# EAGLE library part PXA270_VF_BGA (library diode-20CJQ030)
Intel® PXA270 Processor PXA270 with VF-BGA package 13x13 Features: High-performance processor: -Intel XScale® microarchitecture with Intel® Wireless MMX? Technology -7 Stage pipeline -32 KB instruction cache -32 KB data cache -2 KB "mini" data cache -Extensive data buffering 256 Kbytes of internal SRAM for high speed code or data storage preserved during low-power states High-speed baseband processor interface (Mobile Scalable Link) Rich serial peripheral set: -AC?97 audio port -I2S audio port -USB Client controller -USB Host controller -USB On-The-Go controller -Three high-speed UARTs (two with hardware flow control) -FIR and SIR infrared communications port Hardware debug features ? IEEE JTAG interface with boundary scan Hardware performance-monitoring features with on-chip trace buffer Real-time clock Operating-system timers LCD Controller Universal Subscriber Identity Module interface Low power: -Wireless Intel Speedstep® Technology -Less than 500 mW typical internal dissipation -Supply voltage may be reduced to 0.85 V -Four low-power modes -Dynamic voltage and frequencymanagement High-performance memory controller: -Four banks of SDRAM: up to 104 MHz @ 2.5V, 3.0V, and 3.3V I/O interface -Six static chip selects -Support for PCMCIA and Compact Flash -Companion chip interface Flexible clocking: -CPU clock from 104 to 624 MHz -Flexible memory clock ratios -Frequency changes -Functional clock gating Additional peripherals for system connectivity: -SD Card / MMC Controller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
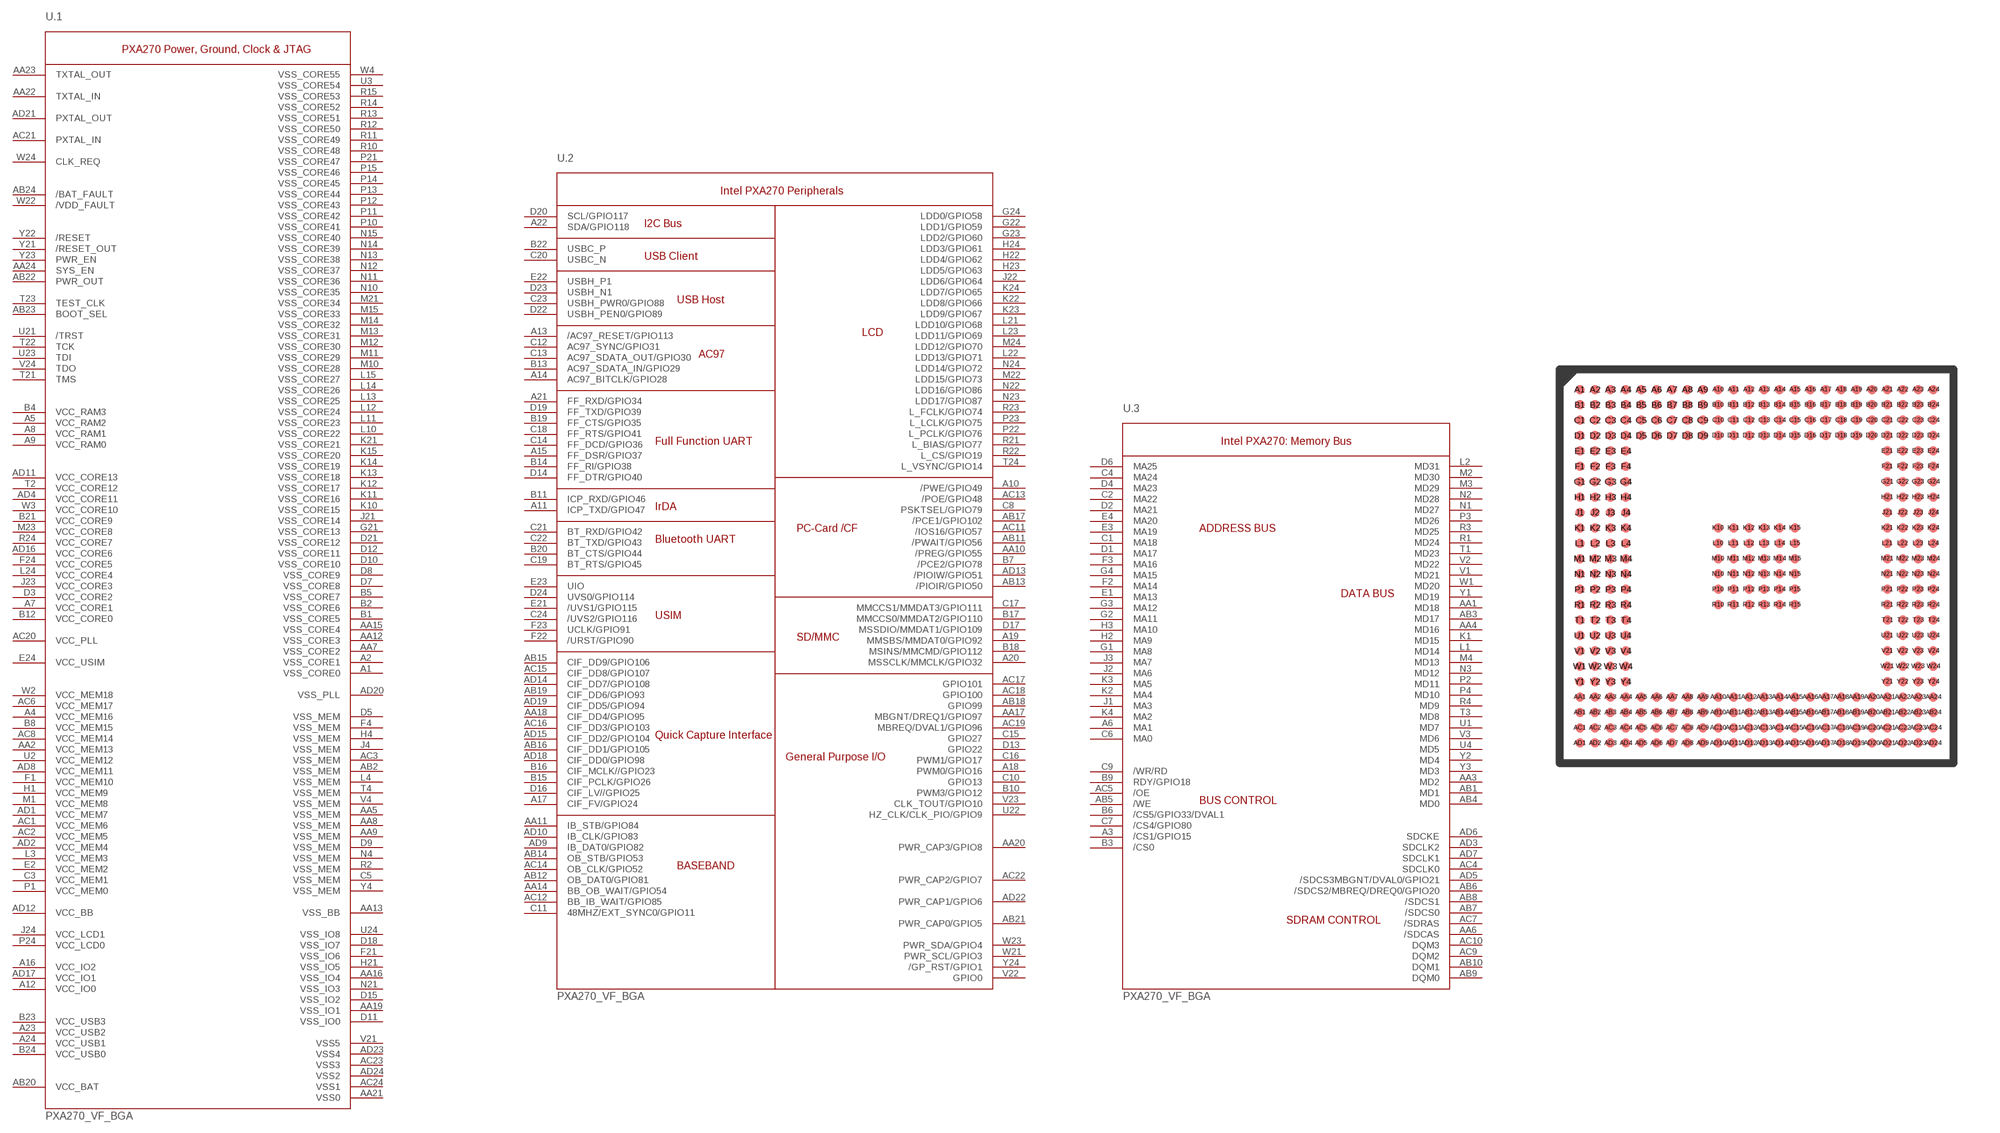
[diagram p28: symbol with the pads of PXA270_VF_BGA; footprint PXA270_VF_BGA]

Designator prefix U; gates .2=PXA270_PERIPHERALS .3=PXA_270_MEM_BUS .1=PXA270_PWR_CLK_13X13

## PXA270_VF_BGA  [PXA270_VF_BGA]
A1  .1:VSS_CORE0  pwr
A2  .1:VSS_CORE1  pwr
A3  .3:/CS1/GPIO15
A4  .1:VCC_MEM16  pwr
A5  .1:VCC_RAM2  pwr
A6  .3:MA1  out
A7  .1:VCC_CORE1  pwr
A8  .1:VCC_RAM1  pwr
A9  .1:VCC_RAM0  pwr
A10  .2:/PWE/GPIO49
A11  .2:ICP_TXD/GPIO47
A12  .1:VCC_IO0  pwr
A13  .2:/AC97_RESET/GPIO113
A14  .2:AC97_BITCLK/GPIO28
A15  .2:FF_DSR/GPIO37
A16  .1:VCC_IO2  pwr
A17  .2:CIF_FV/GPIO24
A18  .2:PWM0/GPIO16
A19  .2:MMSBS/MMDAT0/GPIO92
A20  .2:MSSCLK/MMCLK/GPIO32
A21  .2:FF_RXD/GPIO34
A22  .2:SDA/GPIO118
A23  .1:VCC_USB2  pwr
A24  .1:VCC_USB1  pwr
AA1  .3:MD18
AA2  .1:VCC_MEM13  pwr
AA3  .3:MD2
AA4  .3:MD16
AA5  .1:VSS_MEM  pwr
AA6  .3:/SDCAS  out
AA7  .1:VSS_CORE2  pwr
AA8  .1:VSS_MEM  pwr
AA9  .1:VSS_MEM  pwr
AA10  .2:/PREG/GPIO55
AA11  .2:IB_STB/GPIO84
AA12  .1:VSS_CORE3  pwr
AA13  .1:VSS_BB  pwr
AA14  .2:BB_OB_WAIT/GPIO54
AA15  .1:VSS_CORE4  pwr
AA16  .1:VSS_IO4  pwr
AA17  .2:MBGNT/DREQ1/GPIO97
AA18  .2:CIF_DD4/GPIO95
AA19  .1:VSS_IO1  pwr
AA20  .2:PWR_CAP3/GPIO8
AA21  .1:VSS0  pwr
AA22  .1:TXTAL_IN  in
AA23  .1:TXTAL_OUT  out
AA24  .1:SYS_EN
AB1  .3:MD1
AB2  .1:VSS_MEM  pwr
AB3  .3:MD17
AB4  .3:MD0
AB5  .3:/WE  out
AB6  .3:/SDCS2/MBREQ/DREQ0/GPIO20
AB7  .3:/SDCS0  out
AB8  .3:/SDCS1  out
AB9  .3:DQM0  out
AB10  .3:DQM1  out
AB11  .2:/PWAIT/GPIO56
AB12  .2:OB_DAT0/GPIO81
AB13  .2:/PIOIR/GPIO50
AB14  .2:OB_STB/GPIO53
AB15  .2:CIF_DD9/GPIO106
AB16  .2:CIF_DD1/GPIO105
AB17  .2:/PCE1/GPIO102
AB18  .2:GPIO99
AB19  .2:CIF_DD6/GPIO93
AB20  .1:VCC_BAT  pwr
AB21  .2:PWR_CAP0/GPIO5
AB22  .1:PWR_OUT  out
AB23  .1:BOOT_SEL  in
AB24  .1:/BAT_FAULT  in
AC1  .1:VCC_MEM6  pwr
AC2  .1:VCC_MEM5  pwr
AC3  .1:VSS_MEM  pwr
AC4  .3:SDCLK0  out
AC5  .3:/OE  out
AC6  .1:VCC_MEM17  pwr
AC7  .3:/SDRAS  out
AC8  .1:VCC_MEM14  pwr
AC9  .3:DQM2  out
AC10  .3:DQM3  out
AC11  .2:/IOS16/GPIO57
AC12  .2:BB_IB_WAIT/GPIO85
AC13  .2:/POE/GPIO48
AC14  .2:OB_CLK/GPIO52
AC15  .2:CIF_DD8/GPIO107
AC16  .2:CIF_DD3/GPIO103
AC17  .2:GPIO101
AC18  .2:GPIO100
AC19  .2:MBREQ/DVAL1/GPIO96
AC20  .1:VCC_PLL  pwr
AC21  .1:PXTAL_IN  in
AC22  .2:PWR_CAP2/GPIO7
AC23  .1:VSS3  pwr
AC24  .1:VSS1  pwr
AD1  .1:VCC_MEM7  pwr
AD2  .1:VCC_MEM4  pwr
AD3  .3:SDCLK2  out
AD4  .1:VCC_CORE11  pwr
AD5  .3:/SDCS3MBGNT/DVAL0/GPIO21
AD6  .3:SDCKE  out
AD7  .3:SDCLK1  out
AD8  .1:VCC_MEM11  pwr
AD9  .2:IB_DAT0/GPIO82
AD10  .2:IB_CLK/GPIO83
AD11  .1:VCC_CORE13  pwr
AD12  .1:VCC_BB  pwr
AD13  .2:/PIOIW/GPIO51
AD14  .2:CIF_DD7/GPIO108
AD15  .2:CIF_DD2/GPIO104
AD16  .1:VCC_CORE6  pwr
AD17  .1:VCC_IO1  pwr
AD18  .2:CIF_DD0/GPIO98
AD19  .2:CIF_DD5/GPIO94
AD20  .1:VSS_PLL  pwr
AD21  .1:PXTAL_OUT  out
AD22  .2:PWR_CAP1/GPIO6
AD23  .1:VSS4  pwr
AD24  .1:VSS2  pwr
B1  .1:VSS_CORE5  pwr
B2  .1:VSS_CORE6  pwr
B3  .3:/CS0  out
B4  .1:VCC_RAM3  pwr
B5  .1:VSS_CORE7  pwr
B6  .3:/CS5/GPIO33/DVAL1
B7  .2:/PCE2/GPIO78
B8  .1:VCC_MEM15  pwr
B9  .3:RDY/GPIO18
B10  .2:PWM3/GPIO12
B11  .2:ICP_RXD/GPIO46
B12  .1:VCC_CORE0  pwr
B13  .2:AC97_SDATA_IN/GPIO29
B14  .2:FF_RI/GPIO38
B15  .2:CIF_PCLK/GPIO26
B16  .2:CIF_MCLK//GPIO23
B17  .2:MMCCS0/MMDAT2/GPIO110
B18  .2:MSINS/MMCMD/GPIO112
B19  .2:FF_CTS/GPIO35
B20  .2:BT_CTS/GPIO44
B21  .1:VCC_CORE9  pwr
B22  .2:USBC_P
B23  .1:VCC_USB3  pwr
B24  .1:VCC_USB0  pwr
C1  .3:MA18  out
C2  .3:MA22  out
C3  .1:VCC_MEM1  pwr
C4  .3:MA24  out
C5  .1:VSS_MEM  pwr
C6  .3:MA0  out
C7  .3:/CS4/GPIO80
C8  .2:PSKTSEL/GPIO79
C9  .3:/WR/RD  out
C10  .2:GPIO13
C11  .2:48MHZ/EXT_SYNC0/GPIO11
C12  .2:AC97_SYNC/GPIO31
C13  .2:AC97_SDATA_OUT/GPIO30
C14  .2:FF_DCD/GPIO36
C15  .2:GPIO27
C16  .2:PWM1/GPIO17
C17  .2:MMCCS1/MMDAT3/GPIO111
C18  .2:FF_RTS/GPIO41
C19  .2:BT_RTS/GPIO45
C20  .2:USBC_N
C21  .2:BT_RXD/GPIO42
C22  .2:BT_TXD/GPIO43
C23  .2:USBH_PWR0/GPIO88
C24  .2:/UVS2/GPIO116
D1  .3:MA17  out
D2  .3:MA21  out
D3  .1:VCC_CORE2  pwr
D4  .3:MA23  out
D5  .1:VSS_MEM  pwr
D6  .3:MA25  out
D7  .1:VSS_CORE8  pwr
D8  .1:VSS_CORE9  pwr
D9  .1:VSS_MEM  pwr
D10  .1:VSS_CORE10  pwr
D11  .1:VSS_IO0  pwr
D12  .1:VSS_CORE11  pwr
D13  .2:GPIO22
D14  .2:FF_DTR/GPIO40
D15  .1:VSS_IO2  pwr
D16  .2:CIF_LV//GPIO25
D17  .2:MSSDIO/MMDAT1/GPIO109
D18  .1:VSS_IO7  pwr
D19  .2:FF_TXD/GPIO39
D20  .2:SCL/GPIO117
D21  .1:VSS_CORE12  pwr
D22  .2:USBH_PEN0/GPIO89
D23  .2:USBH_N1
D24  .2:UVS0/GPIO114
E1  .3:MA13  out
E2  .1:VCC_MEM2  pwr
E3  .3:MA19  out
E4  .3:MA20  out
E21  .2:/UVS1/GPIO115
E22  .2:USBH_P1
E23  .2:UIO
E24  .1:VCC_USIM  pwr
F1  .1:VCC_MEM10  pwr
F2  .3:MA14  out
F3  .3:MA16  out
F4  .1:VSS_MEM  pwr
F21  .1:VSS_IO6  pwr
F22  .2:/URST/GPIO90
F23  .2:UCLK/GPIO91
F24  .1:VCC_CORE5  pwr
G1  .3:MA8  out
G2  .3:MA11  out
G3  .3:MA12  out
G4  .3:MA15  out
G21  .1:VSS_CORE13  pwr
G22  .2:LDD1/GPIO59
G23  .2:LDD2/GPIO60
G24  .2:LDD0/GPIO58
H1  .1:VCC_MEM9  pwr
H2  .3:MA9  out
H3  .3:MA10  out
H4  .1:VSS_MEM  pwr
H21  .1:VSS_IO5  pwr
H22  .2:LDD4/GPIO62
H23  .2:LDD5/GPIO63
H24  .2:LDD3/GPIO61
J1  .3:MA3  out
J2  .3:MA6  out
J3  .3:MA7  out
J4  .1:VSS_MEM  pwr
J21  .1:VSS_CORE14  pwr
J22  .2:LDD6/GPIO64
J23  .1:VCC_CORE3  pwr
J24  .1:VCC_LCD1  pwr
K1  .3:MD15
K2  .3:MA4  out
K3  .3:MA5  out
K4  .3:MA2  out
K10  .1:VSS_CORE15  pwr
K11  .1:VSS_CORE16  pwr
K12  .1:VSS_CORE17  pwr
K13  .1:VSS_CORE18  pwr
K14  .1:VSS_CORE19  pwr
K15  .1:VSS_CORE20  pwr
K21  .1:VSS_CORE21  pwr
K22  .2:LDD8/GPIO66
K23  .2:LDD9/GPIO67
K24  .2:LDD7/GPIO65
L1  .3:MD14
L2  .3:MD31
L3  .1:VCC_MEM3  pwr
L4  .1:VSS_MEM  pwr
L10  .1:VSS_CORE22  pwr
L11  .1:VSS_CORE23  pwr
L12  .1:VSS_CORE24  pwr
L13  .1:VSS_CORE25  pwr
L14  .1:VSS_CORE26  pwr
L15  .1:VSS_CORE27  pwr
L21  .2:LDD10/GPIO68
L22  .2:LDD13/GPIO71
L23  .2:LDD11/GPIO69
L24  .1:VCC_CORE4  pwr
M1  .1:VCC_MEM8  pwr
M2  .3:MD30
M3  .3:MD29
M4  .3:MD13
M10  .1:VSS_CORE28  pwr
M11  .1:VSS_CORE29  pwr
M12  .1:VSS_CORE30  pwr
M13  .1:VSS_CORE31  pwr
M14  .1:VSS_CORE32  pwr
M15  .1:VSS_CORE33
M21  .1:VSS_CORE34  pwr
M22  .2:LDD15/GPIO73
M23  .1:VCC_CORE8  pwr
M24  .2:LDD12/GPIO70
N1  .3:MD27
N2  .3:MD28
N3  .3:MD12
N4  .1:VSS_MEM  pwr
N10  .1:VSS_CORE35  pwr
N11  .1:VSS_CORE36  pwr
N12  .1:VSS_CORE37  pwr
N13  .1:VSS_CORE38  pwr
N14  .1:VSS_CORE39  pwr
N15  .1:VSS_CORE40  pwr
N21  .1:VSS_IO3  pwr
N22  .2:LDD16/GPIO86
N23  .2:LDD17/GPIO87
N24  .2:LDD14/GPIO72
P1  .1:VCC_MEM0  pwr
P2  .3:MD11
P3  .3:MD26
P4  .3:MD10
P10  .1:VSS_CORE41  pwr
P11  .1:VSS_CORE42  pwr
P12  .1:VSS_CORE43  pwr
P13  .1:VSS_CORE44  pwr
P14  .1:VSS_CORE45  pwr
P15  .1:VSS_CORE46  pwr
P21  .1:VSS_CORE47  pwr
P22  .2:L_PCLK/GPIO76
P23  .2:L_LCLK/GPIO75
P24  .1:VCC_LCD0  pwr
R1  .3:MD24
R2  .1:VSS_MEM  pwr
R3  .3:MD25
R4  .3:MD9
R10  .1:VSS_CORE48  pwr
R11  .1:VSS_CORE49  pwr
R12  .1:VSS_CORE50  pwr
R13  .1:VSS_CORE51  pwr
R14  .1:VSS_CORE52  pwr
R15  .1:VSS_CORE53  pwr
R21  .2:L_BIAS/GPIO77
R22  .2:L_CS/GPIO19
R23  .2:L_FCLK/GPIO74
R24  .1:VCC_CORE7  pwr
T1  .3:MD23
T2  .1:VCC_CORE12  pwr
T3  .3:MD8
T4  .1:VSS_MEM  pwr
T21  .1:TMS  in
T22  .1:TCK  in
T23  .1:TEST_CLK  in
T24  .2:L_VSYNC/GPIO14
U1  .3:MD7
U2  .1:VCC_MEM12  pwr
U3  .1:VSS_CORE54  pwr
U4  .3:MD5
U21  .1:/TRST  in
U22  .2:HZ_CLK/CLK_PIO/GPIO9
U23  .1:TDI  in
U24  .1:VSS_IO8  pwr
V1  .3:MD21
V2  .3:MD22
V3  .3:MD6
V4  .1:VSS_MEM  pwr
V21  .1:VSS5  pwr
V22  .2:GPIO0
V23  .2:CLK_TOUT/GPIO10
V24  .1:TDO  out
W1  .3:MD20
W2  .1:VCC_MEM18  pwr
W3  .1:VCC_CORE10  pwr
W4  .1:VSS_CORE55  pwr
W21  .2:PWR_SCL/GPIO3
W22  .1:/VDD_FAULT  in
W23  .2:PWR_SDA/GPIO4
W24  .1:CLK_REQ
Y1  .3:MD19
Y2  .3:MD4
Y3  .3:MD3
Y4  .1:VSS_MEM  pwr
Y21  .1:/RESET_OUT  out
Y22  .1:/RESET  in
Y23  .1:PWR_EN  out
Y24  .2:/GP_RST/GPIO1

## Footprint PXA270_VF_BGA (pad centres in mm)
13x13mm VF-BGA Intel® PXA270 Processor Package 0.5mm pitch; 0.3 mm diameter Please send any comments to: messi@users.sourceforge.net
smd 0.3 x 0.3: A1 -5.75,5.75; A2 -5.25,5.75; A3 -4.75,5.75; A4 -4.25,5.75; A5 -3.75,5.75; A6 -3.25,5.75; A7 -2.75,5.75; A8 -2.25,5.75; A9 -1.75,5.75; A10 -1.25,5.75; A11 -0.75,5.75; A12 -0.25,5.75; A13 0.25,5.75; A14 0.75,5.75; A15 1.25,5.75; A16 1.75,5.75; A17 2.25,5.75; A18 2.75,5.75; A19 3.25,5.75; A20 3.75,5.75; A21 4.25,5.75; A22 4.75,5.75; A23 5.25,5.75; A24 5.75,5.75; AA1 -5.75,-4.25; AA2 -5.25,-4.25; AA3 -4.75,-4.25; AA4 -4.25,-4.25; AA5 -3.75,-4.25; AA6 -3.25,-4.25; AA7 -2.75,-4.25; AA8 -2.25,-4.25; AA9 -1.75,-4.25; AA10 -1.25,-4.25; AA11 -0.75,-4.25; AA12 -0.25,-4.25; AA13 0.25,-4.25; AA14 0.75,-4.25; AA15 1.25,-4.25; AA16 1.75,-4.25; AA17 2.25,-4.25; AA18 2.75,-4.25; AA19 3.25,-4.25; AA20 3.75,-4.25; AA21 4.25,-4.25; AA22 4.75,-4.25; AA23 5.25,-4.25; AA24 5.75,-4.25; AB1 -5.75,-4.75; AB2 -5.25,-4.75; AB3 -4.75,-4.75; AB4 -4.25,-4.75; AB5 -3.75,-4.75; AB6 -3.25,-4.75; AB7 -2.75,-4.75; AB8 -2.25,-4.75; AB9 -1.75,-4.75; AB10 -1.25,-4.75; AB11 -0.75,-4.75; AB12 -0.25,-4.75; AB13 0.25,-4.75; AB14 0.75,-4.75; AB15 1.25,-4.75; AB16 1.75,-4.75; AB17 2.25,-4.75; AB18 2.75,-4.75; AB19 3.25,-4.75; AB20 3.75,-4.75; AB21 4.25,-4.75; AB22 4.75,-4.75; AB23 5.25,-4.75; AB24 5.75,-4.75; AC1 -5.75,-5.25; AC2 -5.25,-5.25; AC3 -4.75,-5.25; AC4 -4.25,-5.25; AC5 -3.75,-5.25; AC6 -3.25,-5.25; AC7 -2.75,-5.25; AC8 -2.25,-5.25; AC9 -1.75,-5.25; AC10 -1.25,-5.25; AC11 -0.75,-5.25; AC12 -0.25,-5.25; AC13 0.25,-5.25; AC14 0.75,-5.25; AC15 1.25,-5.25; AC16 1.75,-5.25; AC17 2.25,-5.25; AC18 2.75,-5.25; AC19 3.25,-5.25; AC20 3.75,-5.25; AC21 4.25,-5.25; AC22 4.75,-5.25; AC23 5.25,-5.25; AC24 5.75,-5.25; AD1 -5.75,-5.75; AD2 -5.25,-5.75; AD3 -4.75,-5.75; AD4 -4.25,-5.75; AD5 -3.75,-5.75; AD6 -3.25,-5.75; AD7 -2.75,-5.75; AD8 -2.25,-5.75; AD9 -1.75,-5.75; AD10 -1.25,-5.75; AD11 -0.75,-5.75; AD12 -0.25,-5.75; AD13 0.25,-5.75; AD14 0.75,-5.75; AD15 1.25,-5.75; AD16 1.75,-5.75; AD17 2.25,-5.75; AD18 2.75,-5.75; AD19 3.25,-5.75; AD20 3.75,-5.75; AD21 4.25,-5.75; AD22 4.75,-5.75; AD23 5.25,-5.75; AD24 5.75,-5.75; B1 -5.75,5.25; B2 -5.25,5.25; B3 -4.75,5.25; B4 -4.25,5.25; B5 -3.75,5.25; B6 -3.25,5.25; B7 -2.75,5.25; B8 -2.25,5.25; B9 -1.75,5.25; B10 -1.25,5.25; B11 -0.75,5.25; B12 -0.25,5.25; B13 0.25,5.25; B14 0.75,5.25; B15 1.25,5.25; B16 1.75,5.25; B17 2.25,5.25; B18 2.75,5.25; B19 3.25,5.25; B20 3.75,5.25; B21 4.25,5.25; B22 4.75,5.25; B23 5.25,5.25; B24 5.75,5.25; C1 -5.75,4.75; C2 -5.25,4.75; C3 -4.75,4.75; C4 -4.25,4.75; C5 -3.75,4.75; C6 -3.25,4.75; C7 -2.75,4.75; C8 -2.25,4.75; C9 -1.75,4.75; C10 -1.25,4.75; C11 -0.75,4.75; C12 -0.25,4.75; C13 0.25,4.75; C14 0.75,4.75; C15 1.25,4.75; C16 1.75,4.75; C17 2.25,4.75; C18 2.75,4.75; C19 3.25,4.75; C20 3.75,4.75; C21 4.25,4.75; C22 4.75,4.75; C23 5.25,4.75; C24 5.75,4.75; D1 -5.75,4.25; D2 -5.25,4.25; D3 -4.75,4.25; D4 -4.25,4.25; D5 -3.75,4.25; D6 -3.25,4.25; D7 -2.75,4.25; D8 -2.25,4.25; D9 -1.75,4.25; D10 -1.25,4.25; D11 -0.75,4.25; D12 -0.25,4.25; D13 0.25,4.25; D14 0.75,4.25; D15 1.25,4.25; D16 1.75,4.25; D17 2.25,4.25; D18 2.75,4.25; D19 3.25,4.25; D20 3.75,4.25; D21 4.25,4.25; D22 4.75,4.25; D23 5.25,4.25; D24 5.75,4.25; E1 -5.75,3.75; E2 -5.25,3.75; E3 -4.75,3.75; E4 -4.25,3.75; E21 4.25,3.75; E22 4.75,3.75; E23 5.25,3.75; E24 5.75,3.75; F1 -5.75,3.25; F2 -5.25,3.25; F3 -4.75,3.25; F4 -4.25,3.25; F21 4.25,3.25; F22 4.75,3.25; F23 5.25,3.25; F24 5.75,3.25; G1 -5.75,2.75; G2 -5.25,2.75; G3 -4.75,2.75; G4 -4.25,2.75; G21 4.25,2.75; G22 4.75,2.75; G23 5.25,2.75; G24 5.75,2.75; H1 -5.75,2.25; H2 -5.25,2.25; H3 -4.75,2.25; H4 -4.25,2.25; H21 4.25,2.25; H22 4.75,2.25; H23 5.25,2.25; H24 5.75,2.25; J1 -5.75,1.75; J2 -5.25,1.75; J3 -4.75,1.75; J4 -4.25,1.75; J21 4.25,1.75; J22 4.75,1.75; J23 5.25,1.75; J24 5.75,1.75; K1 -5.75,1.25; K2 -5.25,1.25; K3 -4.75,1.25; K4 -4.25,1.25; K10 -1.25,1.25; K11 -0.75,1.25; K12 -0.25,1.25; K13 0.25,1.25; K14 0.75,1.25; K15 1.25,1.25; K21 4.25,1.25; K22 4.75,1.25; K23 5.25,1.25; K24 5.75,1.25; L1 -5.75,0.75; L2 -5.25,0.75; L3 -4.75,0.75; L4 -4.25,0.75; L10 -1.25,0.75; L11 -0.75,0.75; L12 -0.25,0.75; L13 0.25,0.75; L14 0.75,0.75; L15 1.25,0.75; L21 4.25,0.75; L22 4.75,0.75; L23 5.25,0.75; L24 5.75,0.75; M1 -5.75,0.25; M2 -5.25,0.25; M3 -4.75,0.25; M4 -4.25,0.25; M10 -1.25,0.25; M11 -0.75,0.25; M12 -0.25,0.25; M13 0.25,0.25; M14 0.75,0.25; M15 1.25,0.25; M21 4.25,0.25; M22 4.75,0.25; M23 5.25,0.25; M24 5.75,0.25; N1 -5.75,-0.25; N2 -5.25,-0.25; N3 -4.75,-0.25; N4 -4.25,-0.25; N10 -1.25,-0.25; N11 -0.75,-0.25; N12 -0.25,-0.25; N13 0.25,-0.25; N14 0.75,-0.25; N15 1.25,-0.25; N21 4.25,-0.25; N22 4.75,-0.25; N23 5.25,-0.25; N24 5.75,-0.25; P1 -5.75,-0.75; P2 -5.25,-0.75; P3 -4.75,-0.75; P4 -4.25,-0.75; P10 -1.25,-0.75; P11 -0.75,-0.75; P12 -0.25,-0.75; P13 0.25,-0.75; P14 0.75,-0.75; P15 1.25,-0.75; P21 4.25,-0.75; P22 4.75,-0.75; P23 5.25,-0.75; P24 5.75,-0.75; R1 -5.75,-1.25; R2 -5.25,-1.25; R3 -4.75,-1.25; R4 -4.25,-1.25; R10 -1.25,-1.25; R11 -0.75,-1.25; R12 -0.25,-1.25; R13 0.25,-1.25; R14 0.75,-1.25; R15 1.25,-1.25; R21 4.25,-1.25; R22 4.75,-1.25; R23 5.25,-1.25; R24 5.75,-1.25; T1 -5.75,-1.75; T2 -5.25,-1.75; T3 -4.75,-1.75; T4 -4.25,-1.75; T21 4.25,-1.75; T22 4.75,-1.75; T23 5.25,-1.75; T24 5.75,-1.75; U1 -5.75,-2.25; U2 -5.25,-2.25; U3 -4.75,-2.25; U4 -4.25,-2.25; U21 4.25,-2.25; U22 4.75,-2.25; U23 5.25,-2.25; U24 5.75,-2.25; V1 -5.75,-2.75; V2 -5.25,-2.75; V3 -4.75,-2.75; V4 -4.25,-2.75; V21 4.25,-2.75; V22 4.75,-2.75; V23 5.25,-2.75; V24 5.75,-2.75; W1 -5.75,-3.25; W2 -5.25,-3.25; W3 -4.75,-3.25; W4 -4.25,-3.25; W21 4.25,-3.25; W22 4.75,-3.25; W23 5.25,-3.25; W24 5.75,-3.25; Y1 -5.75,-3.75; Y2 -5.25,-3.75; Y3 -4.75,-3.75; Y4 -4.25,-3.75; Y21 4.25,-3.75; Y22 4.75,-3.75; Y23 5.25,-3.75; Y24 5.75,-3.75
